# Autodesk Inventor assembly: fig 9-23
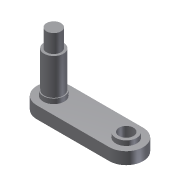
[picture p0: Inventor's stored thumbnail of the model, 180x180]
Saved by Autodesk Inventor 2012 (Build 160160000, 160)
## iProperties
Shininess: 64.0
Length Units: 11269
Angle Units: 11279
Time Units: 11290
Mass Units: 11283
Length Display Precision: 3
Angle Display Precision: 2
Created: 2002-01
Part Number: fig 9-23
Document SubType Name: Assembly
Designer: ***
Density: 0.0
Volumn: 0.0
Area: 0.0
PropertySet Name: Model Information
Control State: 0
Master: False
Checked Out: False
Author: ***
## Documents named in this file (3)
- C:\Users\CadCim\Documents\SAILESH\inventor-2011-fact-prt\c09_inv_2011-prt\c09_inv_2012_prt\fig 9-23.iam
- C:\Users\CadCim\Documents\SAILESH\inventor-2011-fact-prt\c09_inv_2011-prt\c09_inv_2012_prt\Part5.ipt
- C:\Users\CadCim\Documents\SAILESH\inventor-2011-fact-prt\c09_inv_2011-prt\c09_inv_2012_prt\Part6.ipt
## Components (2 placed, 2 different names)
1. Part5:1 — Insert:1
2. Part6:1 — Insert:1
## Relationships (1: Insert 1)
- Insert:1: Part5:1 ↔ Part6:1
